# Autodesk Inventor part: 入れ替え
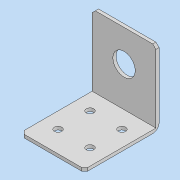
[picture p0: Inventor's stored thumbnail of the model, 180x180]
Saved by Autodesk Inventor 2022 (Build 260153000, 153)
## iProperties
Created: 2021-07
Part Number: 入れ替え
Material: 一般
Document SubType Name: Modeling
Designer: DesignLab
Density: 1 g/cm^3
Appearance: 既定
Author: DesignLab
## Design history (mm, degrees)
sketch "スケッチ1"
  geometry: L1 (0, 0)-(70, 0); L2 (70, 0)-(70, 70); L3 (70, 70)-(0, 70); L4 (0, 70)-(0, 0)
  constraints: 8 end point, 2 parallel, 1 horizontal, 1 perpendicular
  dimensions: "d0" = 70 distance of L3.end L2.end; "d1" = 70 distance of L2.end L1.end
extrude "押し出し1" new body sketch "スケッチ1" taper "d3" = 0 deg; stored distance "全幅" = 60
feature "シェル1" dims "d4" = 3
sketch "スケッチ2"
  geometry: L1 (0, -70)-(60, -70) reference; 3 further points
  constraints: 1 midpoint, 1 vertical alignment
  dimensions: "d5" = 40 distance from line of point (30, -30) L1
hole "穴1" sketch "スケッチ2" at (30, -30) diameter "d6" = 21; stored, may be unused: countersink angle "d10" = 90 deg, drill point angle "d12" = 118 deg; dims "d7" = 6, "d8" = 4, "d9" = 2, "d11" = 8
sketch "スケッチ3"
  geometry: L1 (15, -47)-(45, -47); L2 (45, -47)-(45, -17); L3 (45, -17)-(15, -17); L4 (15, -17)-(15, -47); L5 (15, -47)-(45, -17); L6 (45, -47)-(15, -17); L7 (60, 3)-(0, 3) reference; 4 further points
  constraints: 12 end point, 4 midpoint, 2 parallel, 1 horizontal, 1 perpendicular, 1 vertical alignment
  dimensions: "d13" = 30 distance of L3.end L2.end (= 0.5 x 全幅); "d14" = 30 distance of L2.end L1.end; "d15" = 20 distance between parallel lines of L3 L7
hole "穴2" sketch "スケッチ3" at (15, -47), (15, -17), (45, -17), (45, -47) diameter "d16" = 7; stored, may be unused: countersink angle "d20" = 90 deg, drill point angle "d22" = 118 deg; dims "d17" = 6, "d18" = 4, "d19" = 2, "d21" = 8
chamfer "面取り1" distance "d23" = 3; stored, may be unused: second distance "d24" = 2, angle "d25" = 45 deg
fillet "フィレット1" dims "d26" = 6
node "ソリッド1"
